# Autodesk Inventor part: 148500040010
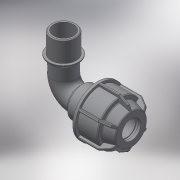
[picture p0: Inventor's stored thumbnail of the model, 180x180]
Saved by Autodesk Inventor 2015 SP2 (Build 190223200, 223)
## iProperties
Created: 2017-08
Part Number: 148500040010
Material: Generic
Description: PLASSON L.14 90° ELBOW MALE ADAPTOR (SILVER) 40-1"
Document SubType Name: Modeling
Designer: KIM
Density: 1 g/cm^3
Appearance: Default
Author: KIM
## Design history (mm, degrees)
derived "148500.ipt"
feature "Solid1::148500.ipt"
feature "Solid2::148500.ipt"
tag "TaggingFeature1"
body "Solid1"
body "Solid2"
other parameters: "d2" = 62, "d4" = 15 deg, "d5" = 40.92, "d6" = 13.5036, "d10" = 73, "d16" = 40.8, "d17" = 3.1, "d22" = 64, "d24" = 3.1, "d25" = 65.7, "d26" = 54.75, "d27" = 3.1, "d28" = 135 deg, "d29" = 1.86, "d31" = 2, "d46" = 150 deg, "d49" = 3.65, "d50" = 0, "d58" = 1.2, "d61" = 360 deg, "d63" = 28, "d94" = 65, "d96" = 36.5739, "d98" = 26.5992, "d99" = 31.08782, "d100" = 135 deg, "d108" = 2, "d112" = 26, "d113" = 86, "d114" = 71.3, "d115" = 31.08782, "d116" = 45 deg, "d117" = 0, "d118" = 0, "d119" = 33.249, "d121" = 39.8988, "d122" = 21, "d123" = 1, "R_" = 33.249, "E_" = 73, "A_" = 86, "l_" = 62, "A_1" = 65
